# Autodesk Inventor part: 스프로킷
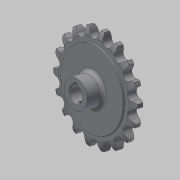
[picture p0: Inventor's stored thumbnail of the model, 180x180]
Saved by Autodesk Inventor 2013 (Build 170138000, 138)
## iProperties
Created: 2016-03
Part Number: 스프로킷
Material: 강철, 탄소
Document SubType Name: Modeling
Designer: mduedu
Density: 7.87 g/cm^3
Mass: 301.818 g
Surface Area: 124.883 cm^2
Volume: 38.3505 cm^3
Author: mduedu
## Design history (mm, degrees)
sketch "스케치1"
  geometry: L1 (0, 5)-(29.5, 5); L2 (29.5, 5)-(29.5, 4.1); L3 (30, 3.6)-(33.625, 3.6); L4 (40, 2)-(40, 0); L5 (40, 0)-(0, 0); L6 (0, 0)-(0, 5); L7 (0, -5)-(29.5, -5); L8 (29.5, -5)-(29.5, -4.1); L9 (30, -3.6)-(33.625, -3.6); L10 (40, -2)-(40, 0); L11 (0, 0)-(0, -5); A1 r 13.5 centre (33.625, -9.9) between (40, 2) and (33.625, 3.6); A2 r 13.5 centre (33.625, 9.9) between (33.625, -3.6) and (40, -2); A3 r 0.5 centre (30, 4.1) between (29.5, 4.1) and (30, 3.6); A4 r 0.5 centre (30, -4.1) between (30, -3.6) and (29.5, -4.1); 2 further points
  constraints: 22 end point, 8 point on circle, 6 symmetric about line, 5 tangent, 4 centre point, 4 parallel, 4 point on line, 1 equal radius, 1 horizontal, 1 perpendicular, 1 other
  dimensions: "d0" = 80 diameter of L4 L6; "d2" = 59 diameter of L2 L6; "d3" = 1.6 vertical distance of L4.start L3.end; "d4" = 3.6 distance from line of L4.end L3; "d5" = 5 distance between parallel lines of L5 L1; "d6" = 13.5 radius of A1; "d15" = 0.5 radius of A3
revolve "회전1" sketch "스케치1" stored, may be unused: angle "d7" = 90 deg
sketch "스케치2" dims "d8" = 65.2, "d11" = 80
  geometry: L1 (0, 0)-(0, 32.6); A1 r 36.57 centre (0, 0) between (-16.231, 32.771) and (0, 36.57); A2 r 3.97 centre (0, 36.57) between (-3.866, 35.665) and (0, 32.6); A3 r 12.7 centre (-16.231, 32.771) between (-3.866, 35.665) and (-5.534, 39.615); A4 r 12.7 centre (16.231, 32.771) between (5.534, 39.615) and (3.866, 35.665); A5 r 3.97 centre (0, 36.57) between (0, 32.6) and (3.866, 35.665); A6 r 40 centre (0, 0) between (5.534, 39.615) and (-5.534, 39.615); 2 further points
  constraints: 12 point on circle, 6 centre point, 4 coincident, 3 symmetric about line, 2 end point, 1 point on line, 1 tangent, 1 vertical, 1 vertical alignment, 7 other
  dimensions: "d10" = 73.14 diameter of A1; "d12" = 12.7 radius of A3
extrude "돌출1" cut sketch "스케치2" stored distance "d13" = 10; taper "d14" = 0 deg
sketch "스케치3"
  geometry: C1 r 11 at (0, 0); 1 further point
  constraints: 1 centre point, 1 coincident
  dimensions: "d19" = 22 diameter of C1
extrude "돌출2" join sketch "스케치3" distance "d20" = 13; taper "d21" = 0 deg
fillet "모깎기1" dims "d22" = 3
sketch "스케치4"
  geometry: L1 (-2, 0)-(2, 0); L2 (2, 0)-(2, 7.8); L3 (2, 7.8)-(-2, 7.8); L4 (-2, 7.8)-(-2, 0); C1 r 6 at (0, 0); 2 further points
  constraints: 8 end point, 2 coincident, 2 parallel, 1 centre point, 1 horizontal, 1 midpoint, 1 perpendicular
  dimensions: "d23" = 12 diameter of C1; "d25" = 4 distance of L2.end L3.end; "d26" = 7.8 distance of L1.end L2.end
extrude "돌출3" cut sketch "스케치4" stored distance "d27" = 8; taper "d28" = 0 deg
chamfer "모따기1" distance "d29" = 0.5; stored, may be unused: second distance "d30" = 2, angle "d31" = 45 deg
node "작업 평면1"
sketch "스케치5"
  geometry: L1 (11, 13)-(-11, 13) reference; 2 further points
  constraints: 1 vertical alignment
  dimensions: "d32" = 4 distance from line of point (0, 9) L1
hole "구멍1" sketch "스케치5" at (0, 9) diameter "d33" = 2.459; stored, may be unused: countersink angle "d37" = 90 deg, drill point angle "d39" = 118 deg; dims "d34" = 6, "d35" = 4, "d36" = 2, "d38" = 8
node "솔리드1"
pattern_circular "원형 패턴1" dims angle "d17" = 360 deg
